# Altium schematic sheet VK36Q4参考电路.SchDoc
size A4
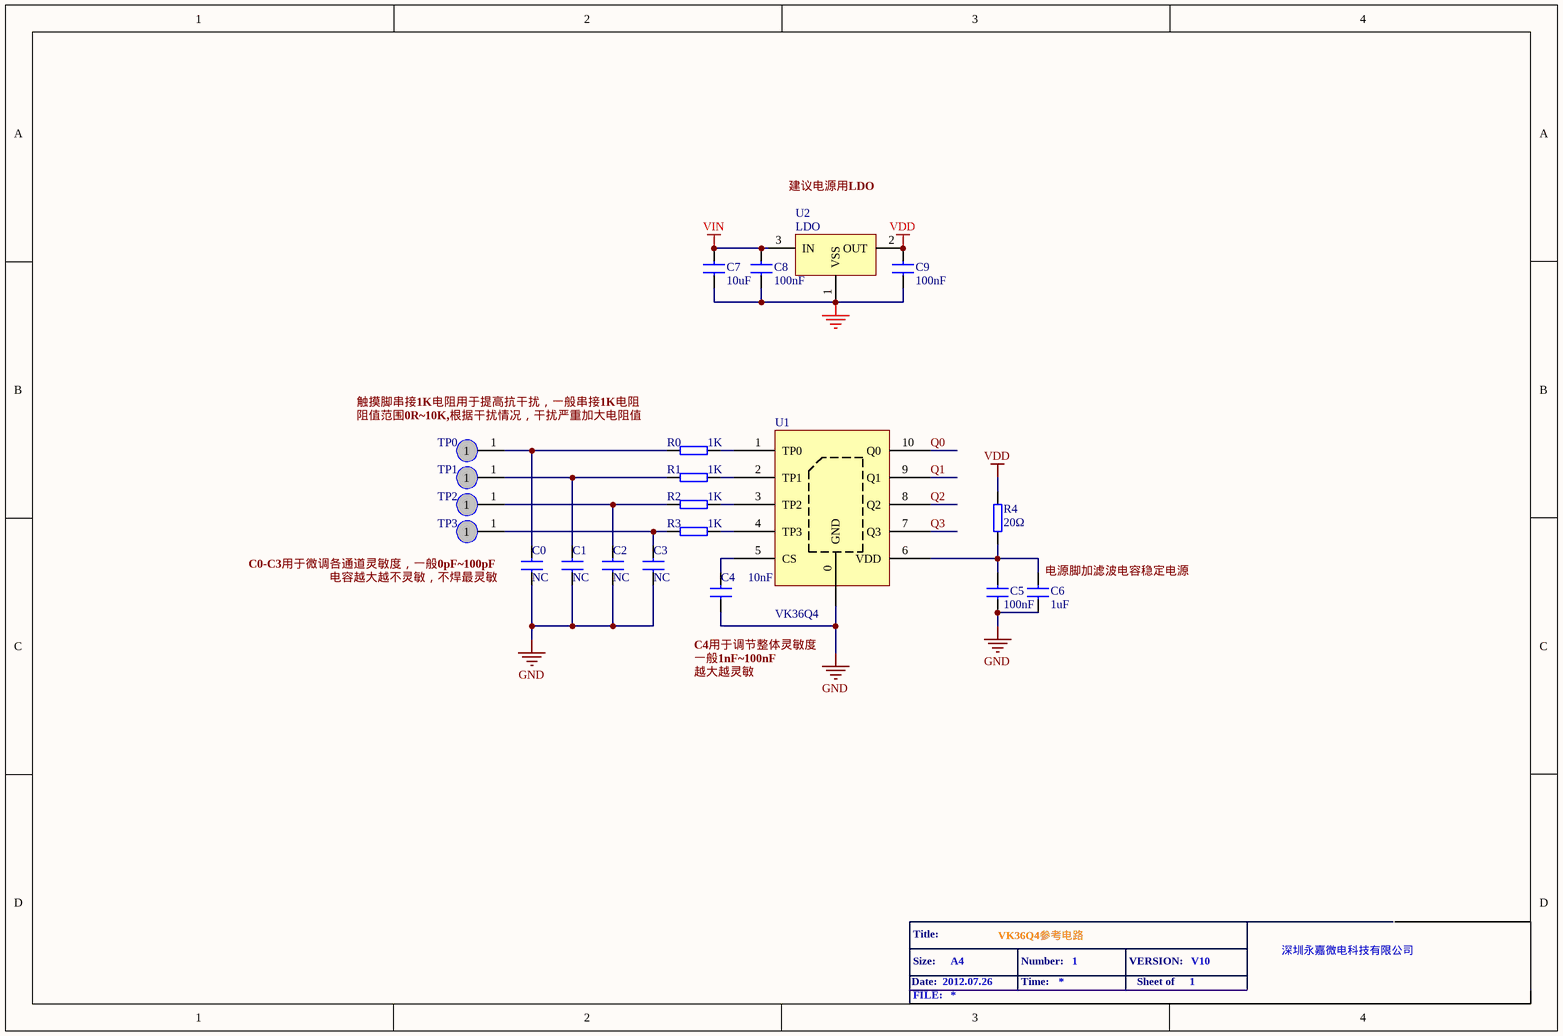
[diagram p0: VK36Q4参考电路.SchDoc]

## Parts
C0  value NC  [0603-C]  (hidden comment: 10uF)
C1  value NC  [0603-C]  (hidden comment: 10uF)
C2  value NC  [0603-C]  (hidden comment: 10uF)
C3  value NC  [0603-C]  (hidden comment: 10uF)
C4  value 10nF  [0603-C]  (hidden comment: 10uF)
C5  100nF  [0603-C]
C6  value 1uF  [0603-C]  (hidden comment: 10uF)
C7  10uF  [0805-C]
C8  100nF  [0805-C]
C9  100nF  [0805-C]
R0  1K  [0603-R]
R1  1K  [0603-R]
R2  1K  [0603-R]
R3  1K  [0603-R]
R4  20Ω  [0603-R]
TP0  TPAD  [TP-PAD0]  (value not drawn)
TP1  TPAD  [TP-PAD0]  (value not drawn)
TP2  TPAD  [TP-PAD0]  (value not drawn)
TP3  TPAD  [TP-PAD0]  (value not drawn)
U1  VK36Q4
U2  LDO  [SOT-23]

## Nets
GND: C0.1 C1.1 C2.1 C3.1 C4.1 C5.2 C6.2 C7.2 C8.2 C9.2 U1.0(GND) U2.1(VSS)
VDD: C9.1 R4.1 U2.2(OUT)
VIN: C7.1 C8.1 U2.3(IN)
Q0: U1.10(Q0)
Q1: U1.9(Q1)
Q2: U1.8(Q2)
Q3: U1.7(Q3)
NetC0_2: C0.2 R0.2 TP0.1
NetC1_2: C1.2 R1.2 TP1.1
NetC2_2: C2.2 R2.2 TP2.1
NetC3_2: C3.2 R3.2 TP3.1
NetC4_2: C4.2 U1.5(CS)
NetC5_1: C5.1 C6.1 R4.2 U1.6(VDD)
NetR0_1: R0.1 U1.1(TP0)
NetR1_1: R1.1 U1.2(TP1)
NetR2_1: R2.1 U1.3(TP2)
NetR3_1: R3.1 U1.4(TP3)

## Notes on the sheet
- 建议电源用LDO
- (near TP0) 触摸脚串接1K电阻用于提高抗干扰，一般串接1K电阻
- (near TP0) 阻值范围0R
  0K,根据干扰情况，干扰严重加大电阻值
- C0-C3用于微调各通道灵敏度，一般0pF
  00pF
- 电容越大越不灵敏，不焊最灵敏
- (near C6) 电源脚加滤波电容稳定电源
- (near C4) C4用于调节整体灵敏度
- 一般1nF
  00nF
- 越大越灵敏
- Date:
- Title:
- Size:
- 2012.07.26
- A4
- VK36Q4参考电路
- Number:
- Time:
- 1
- VERSION:
- Sheet of
- V10
- 深圳永嘉微电科技有限公司
- FILE:

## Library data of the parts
C0-C9 = CAP: Capacitor
R0-R4 = RES: Resistor
TP0-TP3 = TPAD: TESTING
U1 = VK36Q4  DFN10L
U2 = V6206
